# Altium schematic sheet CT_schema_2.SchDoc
size 461 x 297 mm
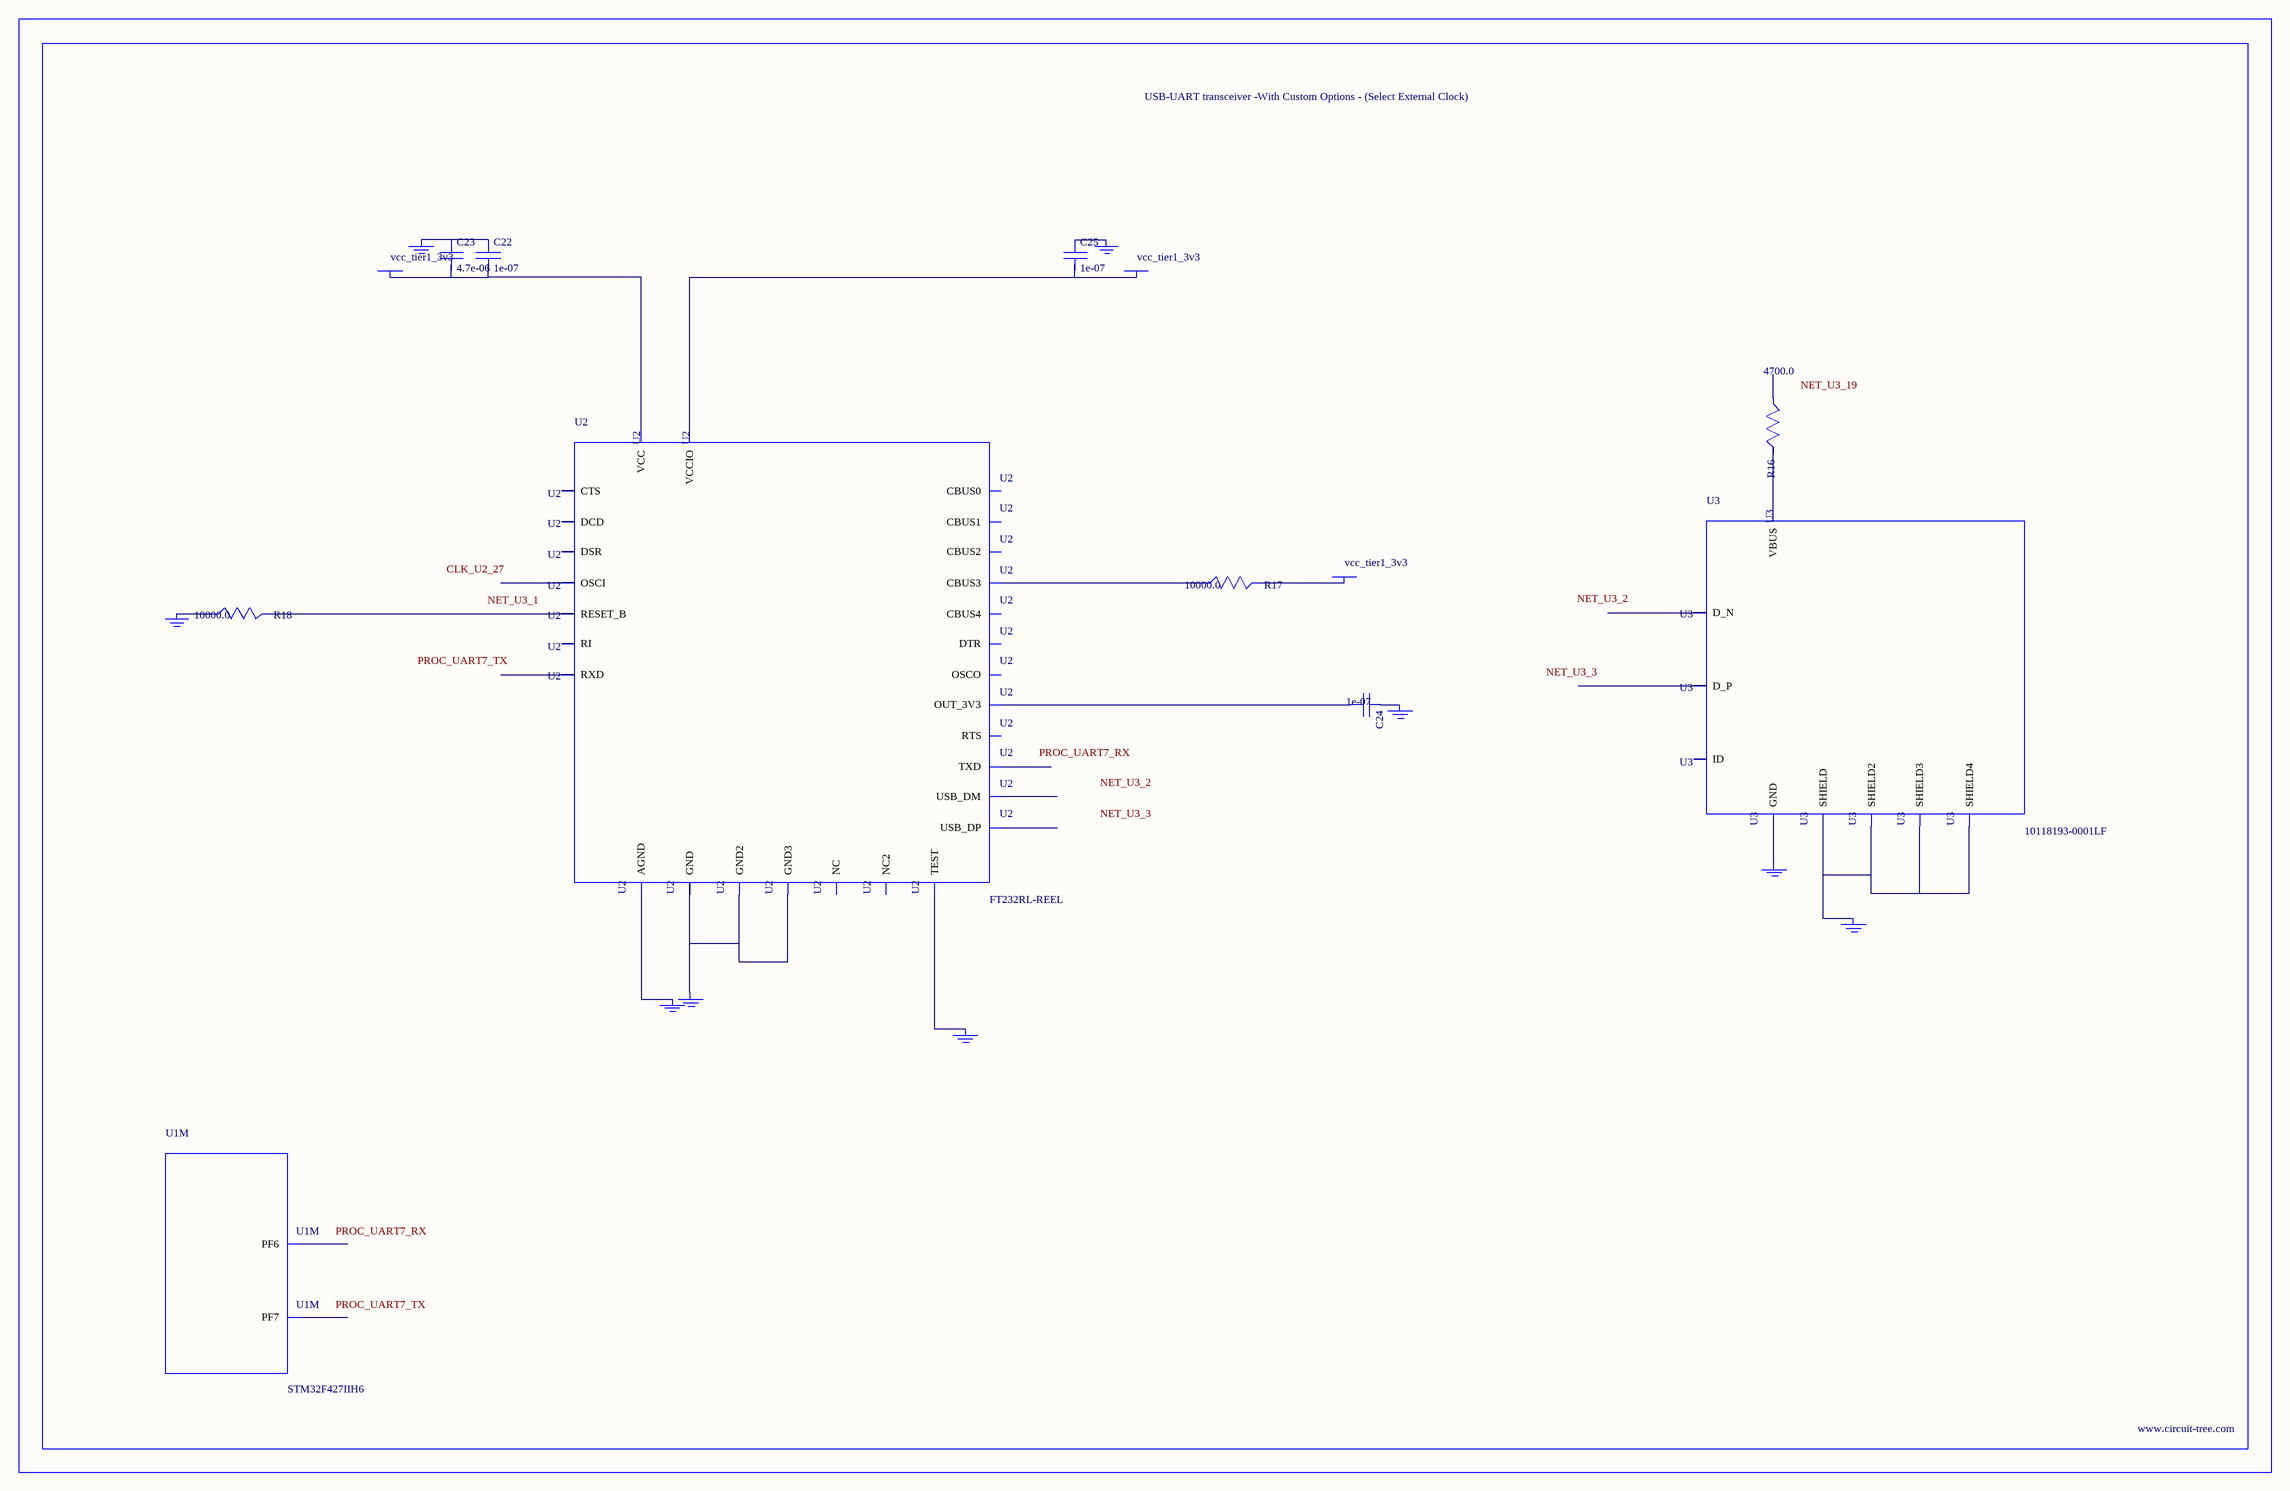
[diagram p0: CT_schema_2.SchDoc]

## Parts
BORDER1  (no value)
C22  1e-07  [C0402]
C23  4.7e-06  [C0805]
C24  1e-07  [C0402]
C25  1e-07  [C0402]
GND_INSTANCE_1_0  (no value)
GND_INSTANCE_1_1  (no value)
GND_INSTANCE_1_2  (no value)
GND_INSTANCE_1_3  (no value)
GND_INSTANCE_1_4  (no value)
GND_INSTANCE_1_5  (no value)
GND_INSTANCE_1_6  (no value)
GND_INSTANCE_1_7  (no value)
GND_INSTANCE_1_8  (no value)
POWER_INSTANCE_1_0  vcc_tier1_3v3
POWER_INSTANCE_1_1  vcc_tier1_3v3
POWER_INSTANCE_1_2  vcc_tier1_3v3
R16  4700.0  [R0603]
R17  10000.0  [R0603]
R18  10000.0  [R0603]
U1  STM32F427IIH6  [UFBGA176_25]  (part M of 17)
U2  FT232RL-REEL  [SSOP-28]
U3  10118193-0001LF  [FCI_10118193-0001LF]

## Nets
NetC22_1: C22.1 C23.1 GND_INSTANCE_1_3.0(GND)
NetC22_2: C22.2 C23.2 POWER_INSTANCE_1_2.0(PWR) U2.20(VCC)
NetC24_1: C24.1 GND_INSTANCE_1_1.0(GND)
NetC24_2: C24.2 U2.17(OUT_3V3)
NetC25_1: C25.1 GND_INSTANCE_1_0.0(GND)
NetC25_2: C25.2 POWER_INSTANCE_1_0.0(PWR) U2.4(VCCIO)
NetGND_INSTANCE_1_2_0: GND_INSTANCE_1_2.0(GND) R18.1
NetGND_INSTANCE_1_4_0: GND_INSTANCE_1_4.0(GND) U2.25(AGND)
NetGND_INSTANCE_1_5_0: GND_INSTANCE_1_5.0(GND) U2.26(TEST)
NetGND_INSTANCE_1_6_0: GND_INSTANCE_1_6.0(GND) U2.7(GND) U2.18(GND2) U2.21(GND3)
NetGND_INSTANCE_1_7_0: GND_INSTANCE_1_7.0(GND) U3.6(SHIELD) U3.7(SHIELD2) U3.8(SHIELD3) U3.9(SHIELD4)
NetGND_INSTANCE_1_8_0: GND_INSTANCE_1_8.0(GND) U3.5(GND)
NetPOWER_INSTANCE_1_1_0: POWER_INSTANCE_1_1.0(PWR) R17.2
NetR16_2: R16.2 U3.1(VBUS)
NetR17_1: R17.1 U2.14(CBUS3)
NetR18_2: R18.2 U2.19(RESET_B)

Not connected (* = marked no-connect by the designer): R16 1; U1 K1(PF7) K2(PF6); U2 1(TXD) 2(DTR) 3(RTS) 5(RXD) 6(RI) 8(NC) 9(DSR) 10(DCD) 11(CTS) 12(CBUS4) 13(CBUS2) 15(USB_DP) 16(USB_DM) 22(CBUS1) 23(CBUS0) 24(NC2) 27(OSCI) 28(OSCO); U3 2(D_N) 3(D_P) 4(ID)

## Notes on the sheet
- Labels drawn without touching a wire or pin: CLK_U2_27, NET_U3_1, NET_U3_2, NET_U3_3, NET_U3_19, PROC_UART7_RX, PROC_UART7_TX

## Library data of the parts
BORDER1 = BORDER_PAGE1
C22 C24 C25 = C0402C104K3RACTU
C23 = C0805C475K4RACTU
GND_INSTANCE_1_0-GND_INSTANCE_1_8 = GND
POWER_INSTANCE_1_0-POWER_INSTANCE_1_2 = PWR
R16 = RC0603JR-074K7L
R17 R18 = RC0603JR-0710KL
